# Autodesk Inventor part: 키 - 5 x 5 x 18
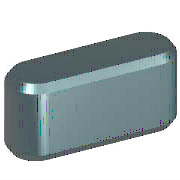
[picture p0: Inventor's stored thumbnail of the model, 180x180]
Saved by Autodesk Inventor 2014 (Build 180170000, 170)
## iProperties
Created: 2012-02
Part Number: 키 - 5 x 5 x 18
Material: 강철, 연강
Description: 키 및 해당 키홈
Document SubType Name: Modeling
Standard: KS B 1311
Designer: mduedu
Standards Organization: KS
Language: ko-KR
Size Designation: 5 x 5 x 18
Categories: <MemberInstance><Categories><Category DisplayName="샤프트 부품" InternalName="7f7aeb1f-a693-4053-b835-cee3144e0d98" Mnemonic="SHFT"><Category DisplayName="키" Interna
Density: 7.86 g/cm^3
Mass: 3.27476 g
Surface Area: 3.57848 cm^2
Volume: 0.416636 cm^3
Appearance: Steel
IsCustomPart: 1
Author: mduedu
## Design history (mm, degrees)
sketch "스케치1"
  geometry: L1 (2.5, 2.5)-(15.5, 2.5); L2 (15.5, -2.5)-(2.5, -2.5); L3 (0, 9.4)-(0, -7.4) reference; L4 (-5, 0)-(30, 0) reference; L5 (18, 0)-(18, 7); A1 r 2.5 centre (2.5, 0) between (2.5, 2.5) and (2.5, -2.5); A2 r 2.5 centre (15.5, 0) between (15.5, -2.5) and (15.5, 2.5)
  constraints: 6 end point, 5 point on circle, 4 tangent, 3 point on line, 2 centre point, 1 horizontal, 1 parallel, 1 perpendicular
  dimensions: "d0" = 2.5 radius of A1 (= 0.5 x PB); "d13" = 2.5 radius of A2 (= 0.5 x PB); "d14" = 18 distance between parallel lines of L5 L3 (= NLG)
extrude "본체1" new body sketch "스케치1" taper "d3" = 0 deg; stored distance "d4" = 10
workplane "Work Plane3"
body "Solid1"
workplane "Work Plane1"
workplane "Work Plane2"
chamfer "모따기1" distance "d8" = 0.4 (= PHH); stored, may be unused: second distance "d9" = 0.4 (= PHH), angle "d15" = 45 deg
other parameters: "d1" = -3 (= -PNT), "d2" = 2 (= PH - PNT), "NLG" = 18 [user parameter; used in 3 equation terms], "PB" = 5 [user parameter; used in 2 equation terms], "PNT" = 3 [user parameter; used in 2 equation terms], "PH" = 5 [user parameter; used in 1 equation term], "PHH" = 0.4 [user parameter; used in 2 equation terms], "d10" = 0, "d16" = 0, "d17" = 0, "d18" = 0, "WDMIN" = 12 [user parameter], "PLB2" = 18 (= NLG) [user parameter], "WDMAX" = 17 [user parameter], "PLB1" = 18 (= NLG) [user parameter], "RR" = 0.16 [user parameter], "PUEB" = 2.3 [user parameter]
